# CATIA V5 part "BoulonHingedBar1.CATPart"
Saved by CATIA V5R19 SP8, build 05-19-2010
Part number: BoulonHingedBar1
Bounding box of the stored display mesh (mm): x -36 to 32, y 592 to 608, z 692 to 708
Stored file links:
  G:\EU_thinkMotion\CFAO_2010\MMS_groupe3\MMS_groupe3\A reprendre\fovide\fovide\BoulonHingedBar1.CATPart
  C:\Users\Rodger\Desktop\Part11.CATPart
  G:\EU_thinkMotion\CFAO_2010\MMS_groupe3\MMS_groupe3\A reprendre\fovide\fovide\fovide.CATProduct
  G:\EU_thinkMotion\CFAO_2010\MMS_groupe3\MMS_groupe3\A reprendre\fovide\fovide\Hinged Bar 15.CATPart
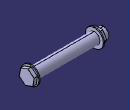
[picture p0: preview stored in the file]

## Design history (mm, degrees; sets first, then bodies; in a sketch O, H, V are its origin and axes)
Parameters
  Diametre = 10 mm
  Longueur = 56 mm
Set1
  DatumSurface1: linked copy from another document
  Point1: linked copy from another document
Body1 (main body)
Body2
  Sketch1 on DatumSurface1, origin (28, 0, 28), H (0, 0, -1), V (0, 1, 0)
    circle A1 centre (-672, 600) radius 8
    point P1 (-672, 600)
    reference projected point E1 (-672, 600) from Point1
    radius A1 = 8 {= Diametre *8/10}
    coincidence: P1 E1
  Pad1: profile Sketch1, direction (1, 0, 0), length 1
  Sketch2 on end face of Pad1, origin (29, 0, 30), H (0, 0, -1), V (0, 1, 0)
    point P1 (-670, 600)
    point P2 (-667.5061, 593.4593)
    point P3 (-663.0887, 598.8894)
    point P4 (-665.5825, 605.4301)
    point P5 (-672.4939, 606.5407)
    point P6 (-676.9113, 601.1106)
    point P7 (-674.4175, 594.5699)
    point P8 (-665.2974, 596.1744)
    line L1 (-667.5061, 593.4593) -> (-663.0887, 598.8894)
    line L2 (-663.0887, 598.8894) -> (-665.5825, 605.4301)
    line L3 (-665.5825, 605.4301) -> (-672.4939, 606.5407)
    line L4 (-672.4939, 606.5407) -> (-676.9113, 601.1106)
    line L5 (-676.9113, 601.1106) -> (-674.4175, 594.5699)
    line L6 (-674.4175, 594.5699) -> (-667.5061, 593.4593)
    construction line L7 (-670, 600) -> (-665.2974, 596.1744)
    construction circle A1 centre (-670, 600) radius 7
    construction arc A2 centre (-676.9113, 601.1106) radius 7 from (-672.4939, 606.5407) to (-674.4175, 594.5699) cw
    construction arc A3 centre (-663.0887, 598.8894) radius 7 from (-665.5825, 605.4301) to (-667.5061, 593.4593) ccw
    reference projected point E1 (-670, 600) from Point1
    radius A1 = 7 {= Diametre *7/10}
    coincidence: A1 P2, A1 P3, A1 P4, A1 P5, A1 P6, A1 P7, A2 P1, A3 P1, P1 E1
    midpoint: P8 L1
    parallelism: L1 L4
  Pad2: profile Sketch2, direction (1, 0, 0), length 3
  Sketch3 on start face of Pad1, origin (28, 0, 28), H (0, 0, -1), V (0, -1, 0)
    circle A1 centre (-672, -600) radius 5
    point P1 (-672, -600)
    reference projected point E1 (-672, -600) from Point1
    radius A1 = 5 {= Diametre /2}
    coincidence: P1 E1
  Pad3: profile Sketch3, direction (-1, 0, 0), length 56 {= Longueur}
  Sketch4 on end face of Pad3, origin (-28, 0, -52), H (0, 0, -1), V (0, -1, 0)
    circle A1 centre (-752, -600) radius 8
    point P1 (-752, -600)
    reference projected point E1 (-752, -600) from Point1
    radius A1 = 8 {= Diametre *8/10}
    coincidence: P1 E1
  Pad4: profile Sketch4, direction (-1, 0, 0), length 1
  Sketch5 on end face of Pad4, origin (-29, 0, -54), H (0, 0, -1), V (0, -1, 0)
    point P1 (-754, -600)
    point P2 (-754.0478, -606.9998)
    point P3 (-747.9619, -603.5413)
    point P4 (-747.9141, -596.5415)
    point P5 (-753.9522, -593.0002)
    point P6 (-760.0381, -596.4587)
    point P7 (-760.0859, -603.4585)
    point P8 (-751.0048, -605.2706)
    line L1 (-754.0478, -606.9998) -> (-747.9619, -603.5413)
    line L2 (-747.9619, -603.5413) -> (-747.9141, -596.5415)
    line L3 (-747.9141, -596.5415) -> (-753.9522, -593.0002)
    line L4 (-753.9522, -593.0002) -> (-760.0381, -596.4587)
    line L5 (-760.0381, -596.4587) -> (-760.0859, -603.4585)
    line L6 (-760.0859, -603.4585) -> (-754.0478, -606.9998)
    construction line L7 (-754, -600) -> (-751.0048, -605.2706)
    construction circle A1 centre (-754, -600) radius 7
    construction arc A2 centre (-760.0381, -596.4587) radius 7 from (-753.9522, -593.0002) to (-760.0859, -603.4585) cw
    construction arc A3 centre (-747.9619, -603.5413) radius 7 from (-747.9141, -596.5415) to (-754.0478, -606.9998) ccw
    reference projected point E1 (-754, -600) from Point1
    radius A1 = 7 {= Diametre *7/10}
    coincidence: A1 P2, A1 P3, A1 P4, A1 P5, A1 P6, A1 P7, A2 P1, A3 P1, P1 E1
    midpoint: P8 L1
    parallelism: L1 L4
  Pad5: profile Sketch5, direction (-1, 0, 0), length 3
  Sketch6 on end face of Pad5, origin (-32, 0, -60), H (0, 0, -1), V (0, -1, 0)
    circle A1 centre (-760, -600) radius 5
    point P1 (-760, -600)
    reference projected point E1 (-760, -600) from Point1
    radius A1 = 5 {= Diametre /2}
    coincidence: P1 E1
  Pad6: profile Sketch6, direction (-1, 0, 0), length 4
